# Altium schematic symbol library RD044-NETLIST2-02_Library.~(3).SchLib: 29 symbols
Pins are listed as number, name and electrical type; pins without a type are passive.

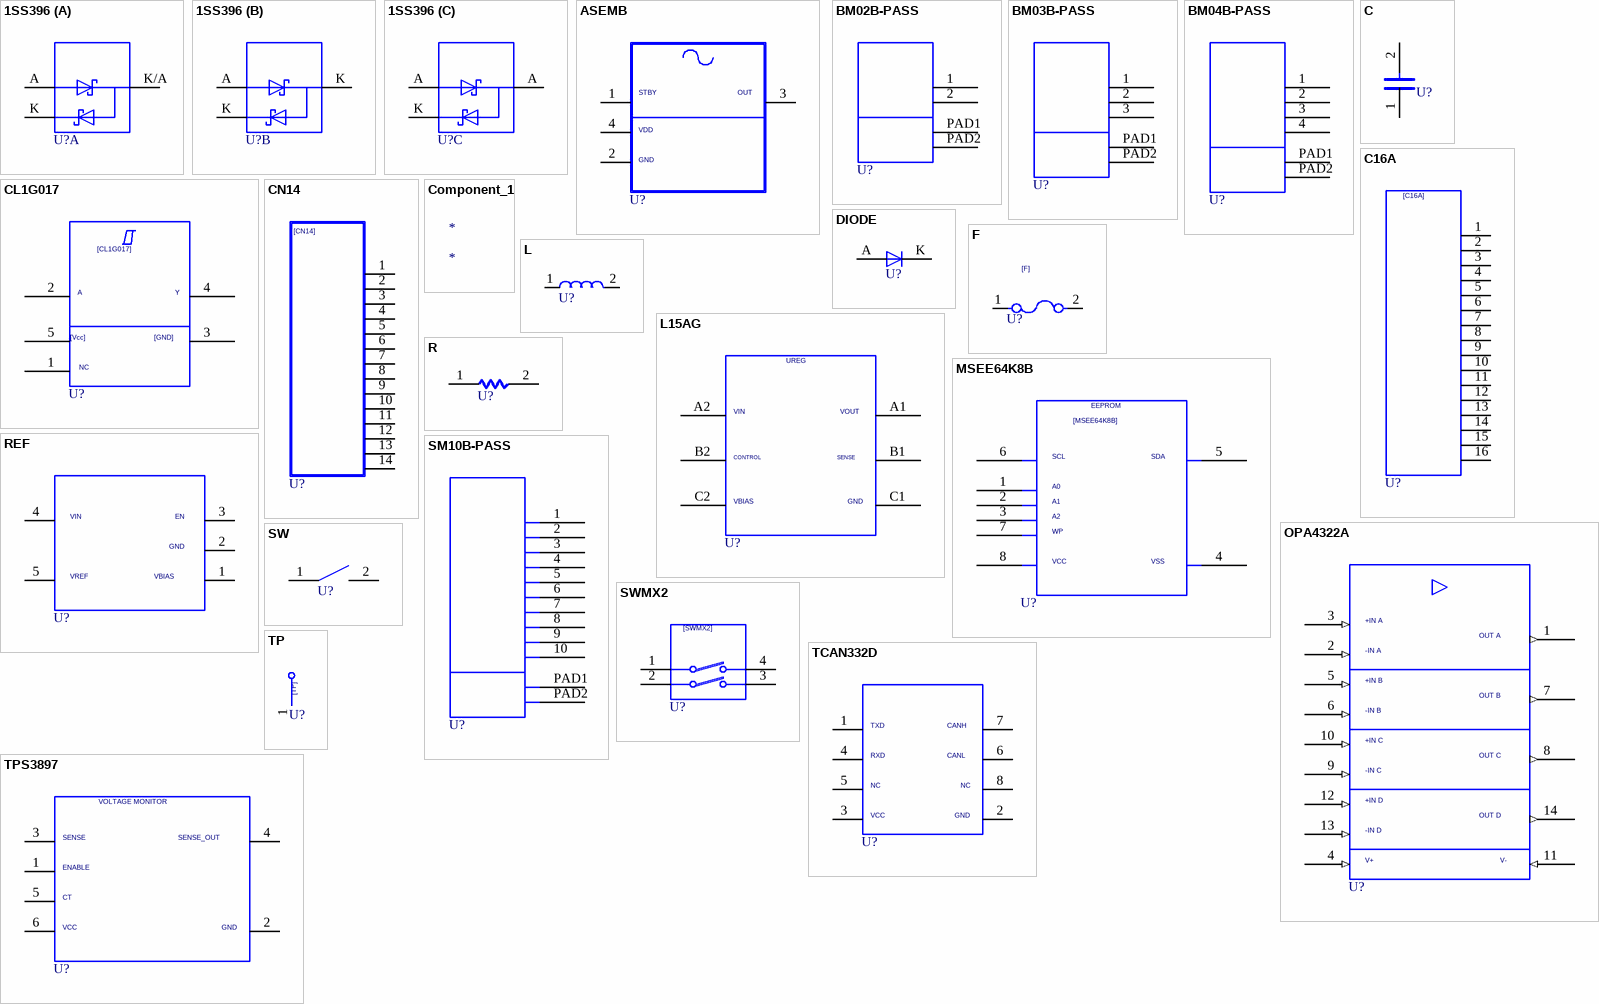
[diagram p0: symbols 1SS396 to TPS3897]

## 1SS396
designator U?  (value not drawn)
SAVECOUNT: 7; SAVEAREA0: -5465,-437,27678,21425; TIME: 18:51:12; UPDATEUSER: cae; UPDATETIME: 10:39:29; OriginalSymbolOrigin: (5080,17780); Altium-Right: 50; Altium-Bottom: 60
part A pins: A, K, K/A
part B pins: A, K, K K/A
part C pins: A, A K/A, K

## ASEMB
designator U?  (value not drawn)
SAVEAREA0: -13388,-318,46493,30783; TIME: 14:56:21; UPDATEUSER: cae; UPDATETIME: 14:57:23; SAVECOUNT: 2; OriginalSymbolOrigin: (5080,27940); Altium-Right: 90; Altium-Bottom: 100
pins: 1, 2, 3, 4

## BM02B-PASS
designator U?  (value not drawn)
SAVEAREA0: -14137,-269,36664,26115; SAVECOUNT: 27; TIME: 13:28:28; UPDATEUSER: cae; UPDATETIME: 09:55:50; OriginalSymbolOrigin: (2540,22860); Altium-Right: 50; Altium-Bottom: 80
pins: 1, 2, PAD1, PAD2

## BM03B-PASS
designator U?  (value not drawn)
SAVEAREA0: -16734,-4275,39145,32584; SAVECOUNT: 25; TIME: 13:28:28; UPDATEUSER: cae; UPDATETIME: 09:56:18; OriginalSymbolOrigin: (2540,25400); Altium-Right: 50; Altium-Bottom: 90
pins: 1, 2, 3, PAD1, PAD2

## BM04B-PASS
designator U?  (value not drawn)
SAVEAREA0: -19221,-4664,41739,35547; SAVECOUNT: 23; TIME: 13:28:28; UPDATEUSER: cae; UPDATETIME: 09:56:44; OriginalSymbolOrigin: (2540,27940); Altium-Right: 50; Altium-Bottom: 100
pins: 1, 2, 3, 4, PAD1, PAD2

## C
designator U?  (value not drawn)
OriginalSymbolOrigin: (2540,7620); Altium-Right: 20; Altium-Bottom: 10
pins: 1, 2

## C16A
designator U?  (value not drawn)
SAVEAREA0: -32851,-599,52300,52191; TIME: 12:01:18; UPDATEUSER: fukuda-y; UPDATETIME: 13:44:49; SAVECOUNT: 2; OriginalSymbolOrigin: (2540,48260); Altium-Right: 50; Altium-Bottom: 190
pins: 1, 2, 3, 4, 5, 6, 7, 8, 9, 10, 11, 12, 13, 14, 15, 16

## CL1G017
designator U?  (value not drawn)
TIME: 16:09:43; UPDATEUSER: tomizawa-y; UPDATETIME: 12:13:51; SAVECOUNT: 12; SAVEAREA0: -8892,-376,44463,33313; OriginalSymbolOrigin: (7620,30480); Altium-Right: 80; Altium-Bottom: 110
pins: 1, 2, 3, 4, 5

## CN14
designator U?  (value not drawn)
OriginalSymbolOrigin: (2540,45720); Altium-Right: 50; Altium-Bottom: 180
pins: 1, 2, 3, 4, 5, 6, 7, 8, 9, 10, 11, 12, 13, 14

## Component_1
designator *

## DIODE
designator U?  (value not drawn)
SAVEAREA0: -1337,-97,13924,7829; SAVECOUNT: 4; TIME: 14:49:55; UPDATEUSER: cae; UPDATETIME: 13:41:08; OriginalSymbolOrigin: (5080,5080); Altium-Right: 10; Altium-Bottom: 20
pins: A, K

## F
designator U?  (value not drawn)
OriginalSymbolOrigin: (2540,5080); Altium-Right: 40; Altium-Bottom: 20
pins: 1, 2

## L
designator U?  (value not drawn)
OriginalSymbolOrigin: (2540,5080); Altium-Right: 30; Altium-Bottom: 20
pins: 1, 2

## L15AG
designator U?  (value not drawn)
TIME: 08:44:39; UPDATEUSER: cae; UPDATETIME: 13:17:54; SAVECOUNT: 102; SAVEAREA0: -14581,-371,55282,35914; OriginalSymbolOrigin: (7620,33020); Altium-Right: 100; Altium-Bottom: 120
pins: A1, A2, B1, B2, C1, C2

## MSEE64K8B
designator U?  (value not drawn)
SAVECOUNT: 8; SAVEAREA0: -9998,-458,55119,39162; TIME: 10:18:07; UPDATEUSER: 19990028; UPDATETIME: 09:15:23; OriginalSymbolOrigin: (7620,35560); Altium-Right: 120; Altium-Bottom: 130
pins: 1, 2, 3, 4, 5, 6, 7, 8

## OPA4322A
designator U?  (value not drawn)
SAVECOUNT: 28; SAVEAREA0: -34439,-609,80338,59004; TIME: 15:40:02; UPDATEUSER: cae; UPDATETIME: 16:49:13; OriginalSymbolOrigin: (7620,55880); Altium-Right: 120; Altium-Bottom: 210
pins: 1 (out), 2 (in), 3 (in), 4 (in), 5 (in), 6 (in), 7 (out), 8 (out), 9 (in), 10 (in), 11 (in), 12 (in), 13 (in), 14 (out)

## R
designator U?  (value not drawn)
OriginalSymbolOrigin: (5080,5080); Altium-Right: 20
pins: 1, 2

## REF
designator U?  (value not drawn)
SAVECOUNT: 25; SAVEAREA0: -10386,-296,45494,28727; TIME: 17:47:02; UPDATEUSER: cae; UPDATETIME: 11:05:59; OriginalSymbolOrigin: (5080,25400); Altium-Right: 100; Altium-Bottom: 90
pins: 1, 2, 3, 4, 5

## SM10B-PASS
designator U?  (value not drawn)
SAVEAREA0: -33411,-485,58033,47009; SAVECOUNT: 23; TIME: 13:28:28; UPDATEUSER: cae; UPDATETIME: 14:27:01; OriginalSymbolOrigin: (2540,43180); Altium-Right: 60; Altium-Bottom: 160
pins: 1, 2, 3, 4, 5, 6, 7, 8, 9, 10, PAD1, PAD2

## SW
designator U?  (value not drawn)
SAVEAREA0: -3361,-153,18383,13055; SAVECOUNT: 49; TIME: 15:02:55; UPDATEUSER: fukuda-y; UPDATETIME: 10:01:15; OriginalSymbolOrigin: (5080,5080); Altium-Right: 20
pins: 1, 2

## SWMX2
designator U?  (value not drawn)
OriginalSymbolOrigin: (5080,15240); Altium-Right: 50
pins: 1, 2, 3, 4

## TCAN332D
designator U?  (value not drawn)
SAVECOUNT: 26; SAVEAREA0: -15475,-323,45487,31339; TIME: 17:47:02; UPDATEUSER: cae; UPDATETIME: 14:38:54; OriginalSymbolOrigin: (5080,27940); Altium-Right: 80; Altium-Bottom: 100
pins: 1, 2, 3, 4, 5, 6, 7, 8

## TP
designator U?  (value not drawn)
TIME: 16:12:21; UPDATEUSER: fukuda-y; UPDATETIME: 16:18:11; SAVECOUNT: 2; SAVEAREA0: -242,-92,12810,7836; OriginalSymbolOrigin: (0,7620); Altium-Right: 20; Altium-Bottom: 30
pins: 1

## TPS3897
designator U?  (value not drawn)
SAVEAREA0: -10817,-344,54055,33349; TIME: 16:54:57; UPDATEUSER: cae; UPDATETIME: 13:48:08; SAVECOUNT: 66; OriginalSymbolOrigin: (5080,30480); Altium-Right: 130; Altium-Bottom: 110
pins: 1, 2, 3, 4, 5, 6

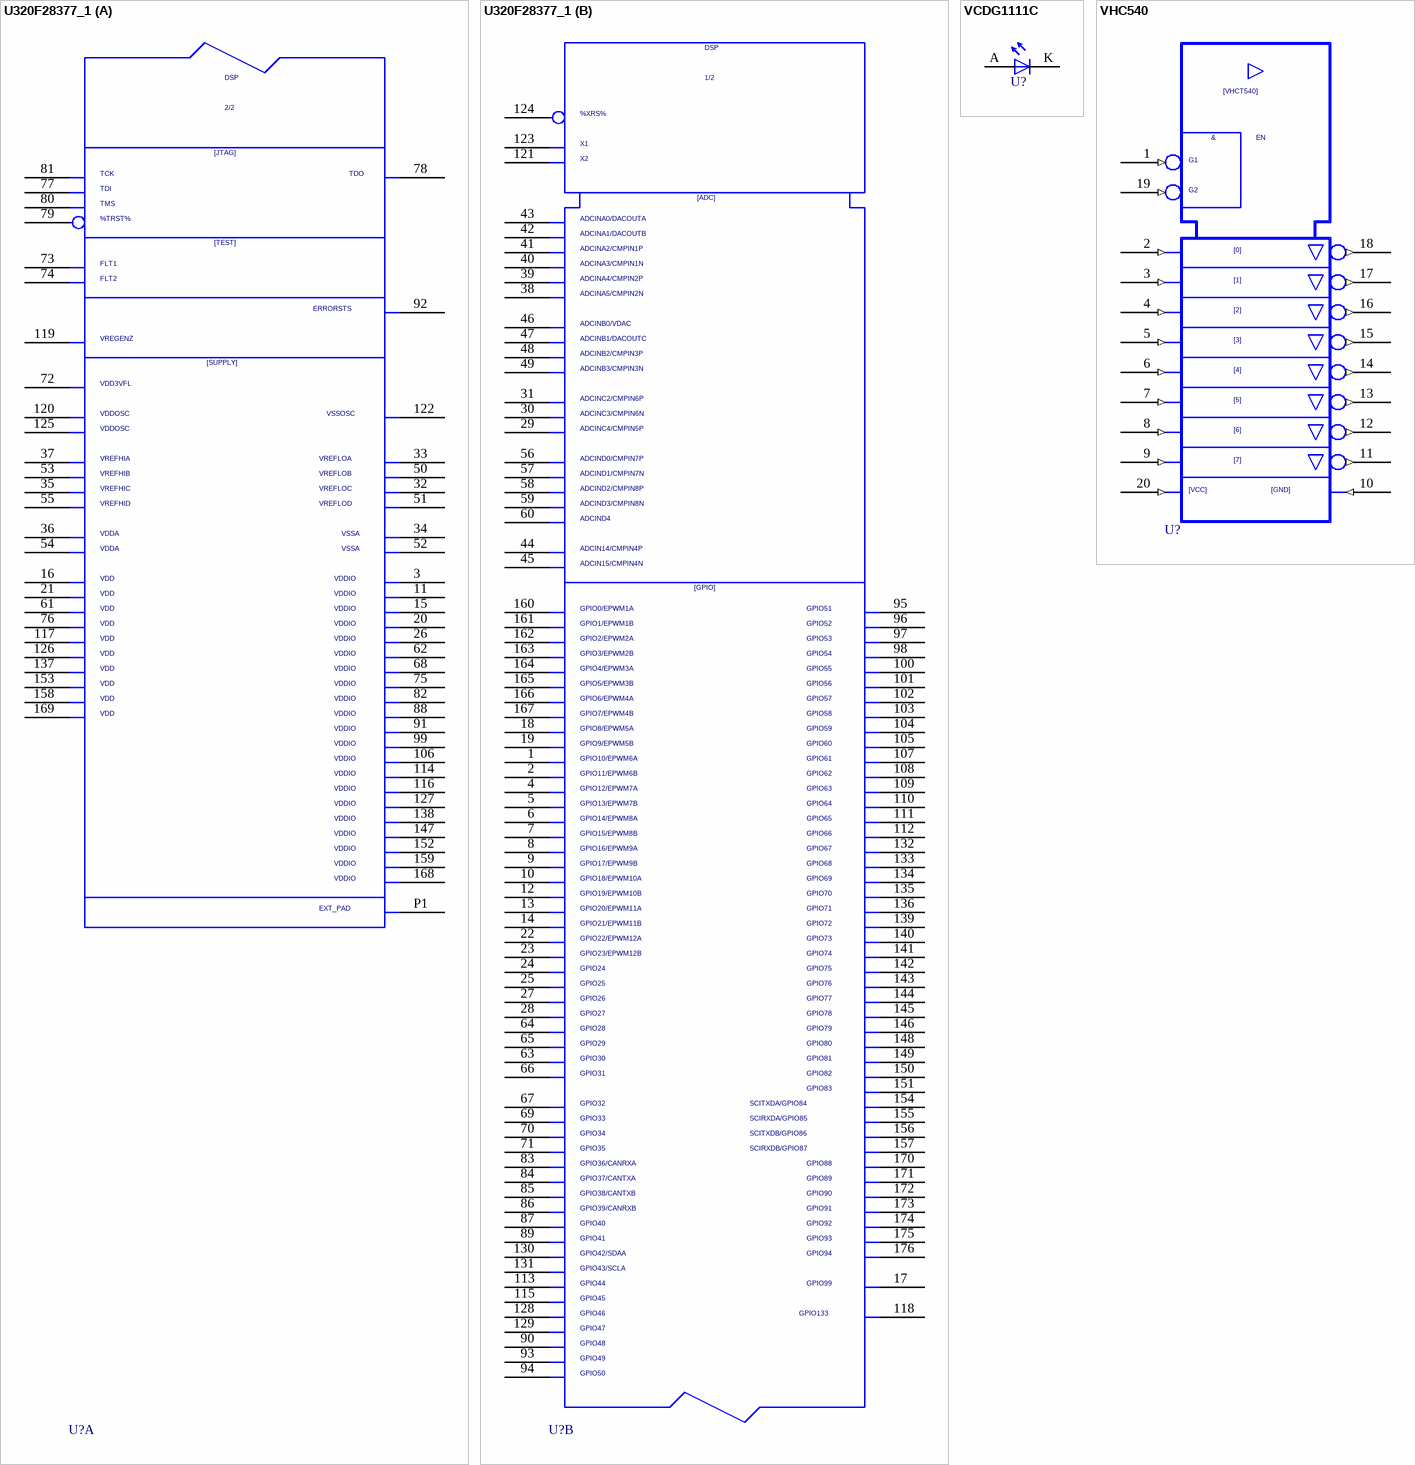
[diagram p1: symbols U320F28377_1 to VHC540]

## U320F28377_1
designator U?  (value not drawn)
SAVEAREA0: -157495,-2464,228972,238585; SAVECOUNT: 59; TIME: 10:04:23; UPDATEUSER: cae; UPDATETIME: 18:05:54; OriginalSymbolOrigin: (7620,233680); Altium-Right: 220; Altium-Bottom: 590; Altium-Bottom1: 920
part A pins: 3, 11, 15, 16, 20, 21, 26, 32, 33, 34, 35, 36, 37, 50, 51, 52, 53, 54, 55, 61, 62, 68, 72, 73, 74, 75, 76, 77, 78, 79, 80, 81, 82, 88, 91, 92, 99, 106, 114, 116, 117, 119, 120, 122, 125, 126, 127, 137, 138, 147, 152, 153, 158, 159, 168, 169, P1
part B pins: 1, 2, 4, 5, 6, 7, 8, 9, 10, 12, 13, 14, 17, 18, 19, 22, 23, 24, 25, 27, 28, 29, 30, 31, 38, 39, 40, 41, 42, 43, 44, 45, 46, 47, 48, 49, 56, 57, 58, 59, 60, 63, 64, 65, 66, 67, 69, 70, 71, 83, 84, 85, 86, 87, 89, 90, 93, 94, 95, 96, 97, 98, 100, 101, 102, 103, 104, 105, 107, 108, 109, 110, 111, 112, 113, 115, 118, 121, 123, 124, 128, 129, 130, 131, 132, 133, 134, 135, 136, 139, 140, 141, 142, 143, 144, 145, 146, 148, 149, 150, 151, 154, 155, 156, 157, 160, 161, 162, 163, 164, 165, 166, 167, 170, 171, 172, 173, 174, 175, 176

## VCDG1111C
designator U?  (value not drawn)
SAVEAREA0: -6769,-859,19276,16321; TIME: 14:49:55; UPDATEUSER: cae; UPDATETIME: 10:51:12; SAVECOUNT: 5; OriginalSymbolOrigin: (5080,7620); Altium-Right: 10; Altium-Bottom: 30
pins: A, K

## VHC540
designator U?  (value not drawn)
SAVEAREA0: -64373,-927,110287,89788; TIME: 09:37:32; UPDATEUSER: cae; SAVECOUNT: 1; OriginalSymbolOrigin: (7620,83820); Altium-Right: 120; Altium-Bottom: 320
pins: 1 (in), 2 (in), 3 (in), 4 (in), 5 (in), 6 (in), 7 (in), 8 (in), 9 (in), 10 (in), 11 (out), 12 (out), 13 (out), 14 (out), 15 (out), 16 (out), 17 (out), 18 (out), 19 (in), 20 (in)

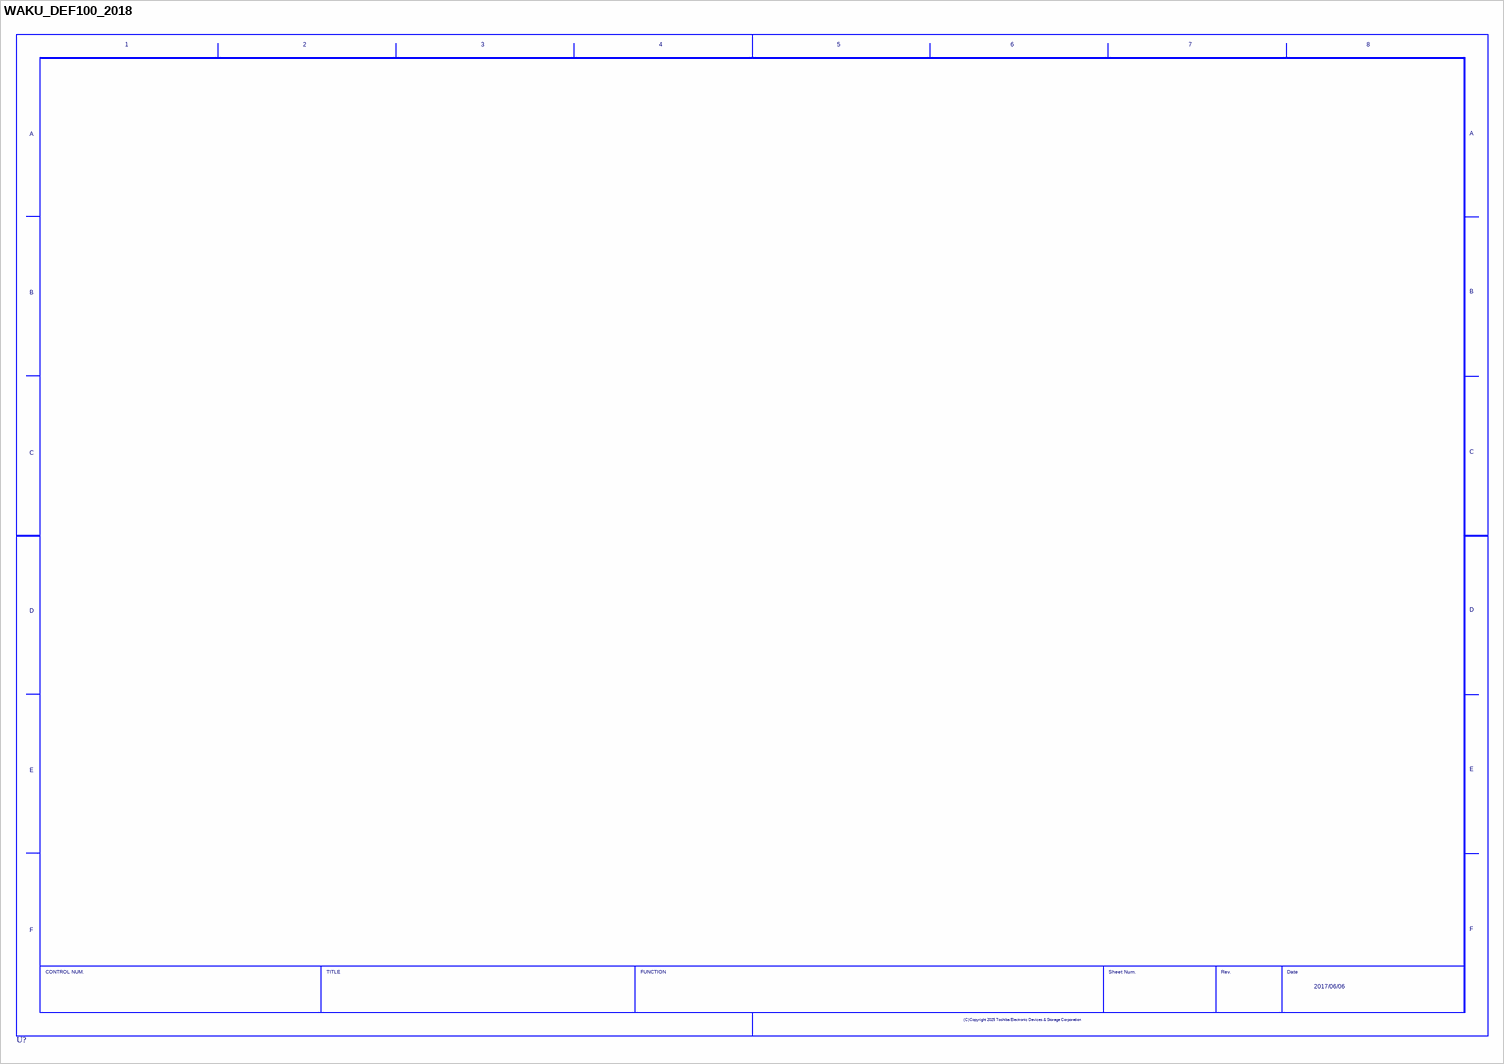
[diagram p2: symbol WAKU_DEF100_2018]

## WAKU_DEF100_2018
designator U?  DATE: 2017/06/06  (hidden comment: WAKU_DEF100_2018)
PLOTTIME: HH:MM; SAVEAREA0: -113565,-16950,524772,314592; TIME: 14:30:25; UPDATEUSER: t5459927; UPDATETIME: 11:38:33; SAVECOUNT: 5; OriginalSymbolOrigin: (10160,284480); Altium-Right: 1570; Altium-Bottom: 1070

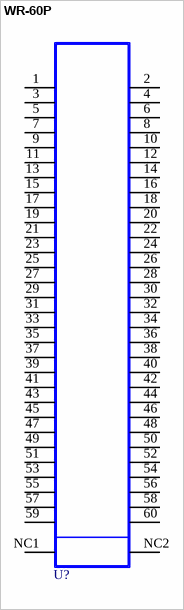
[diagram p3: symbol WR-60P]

## WR-60P
designator U?  (value not drawn)
SAVEAREA0: -67682,-998,88845,96631; SAVECOUNT: 3; TIME: 09:42:27; UPDATEUSER: cae; UPDATETIME: 10:25:54; OriginalSymbolOrigin: (5080,91440); Altium-Right: 50; Altium-Bottom: 350
pins: 1, 2, 3, 4, 5, 6, 7, 8, 9, 10, 11, 12, 13, 14, 15, 16, 17, 18, 19, 20, 21, 22, 23, 24, 25, 26, 27, 28, 29, 30, 31, 32, 33, 34, 35, 36, 37, 38, 39, 40, 41, 42, 43, 44, 45, 46, 47, 48, 49, 50, 51, 52, 53, 54, 55, 56, 57, 58, 59, 60, NC1, NC2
